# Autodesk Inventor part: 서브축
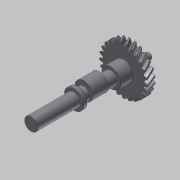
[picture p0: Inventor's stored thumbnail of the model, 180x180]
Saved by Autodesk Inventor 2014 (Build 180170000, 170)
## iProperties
Created: 2018-07
Part Number: 서브축
Material: 강철
Document SubType Name: Modeling
Designer: mduedu
Categories: <?xml version="1.0" encoding="UTF-16"?> <MemberInstance><Categories><FamilyTemplate><FamilyTemplateParameter ValueType="xs:double" Id="1" ObjectReferenceKey="da
Density: 7.85 g/cm^3
Mass: 513.764 g
Surface Area: 178.04 cm^2
Volume: 65.4477 cm^3
Appearance: 강철
CustomPartVersion: 1
Author: mduedu
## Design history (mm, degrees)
sketch "Sketch1"
  geometry: C1 r 30.864 at (0, 0)
  constraints: 1 centre point
  dimensions: "d0" = 61.72879 diameter of C1 (= da_da)
extrude "Extrusion1" new body sketch "Sketch1" distance "d1" = 10 (= da_b); taper "d2" = 0 deg
workplane "Work Plane2"
sketch "Sketch2"
  geometry: C1 r 30.864 at (0, 0) reference; C2 r 29.013 at (0, 0)
  constraints: 1 centre point, 1 coincident
  dimensions: "d3" = 58.02632 diameter of C2 (= da_dw)
feature "피치 지름" sketch "Sketch2" dims "d4" = 10, "d5" = 0
workplane "Work Plane8"
workplane "Work Plane9"
feature "스퍼 기어" dims "da_b" = 10, "da_d" = 57.73503, "da_aw" = 44.1, "da_da" = 61.72879, "da_df" = 52.73503, "da_dw" = 58.02632, angle "da_beta" = 30 deg, "da_lefttooth" = 10, "da_righttooth" = 0
sketch "스케치3"
  geometry: C1 r 12.5 at (0, 0); 1 further point
  constraints: 1 centre point, 1 coincident
  dimensions: "d49" = 25 diameter of C1
extrude "돌출2" join sketch "스케치3" distance "d50" = 16; taper "d51" = 0 deg
sketch "스케치4"
  geometry: C1 r 8.5 at (0, 0); 1 further point
  constraints: 1 centre point, 1 coincident
  dimensions: "d52" = 17 diameter of C1
extrude "돌출3" join sketch "스케치4" distance "d53" = 103; taper "d54" = 0 deg
sketch "스케치5"
  geometry: C1 r 7.5 at (0, 0); 1 further point
  constraints: 1 centre point, 1 coincident
  dimensions: "d55" = 15 diameter of C1
extrude "돌출4" join sketch "스케치5" distance "d56" = 16; taper "d57" = 0 deg
sketch "스케치6"
  geometry: C1 r 4 at (0, 0); 1 further point
  constraints: 1 centre point, 1 coincident
  dimensions: "d58" = 8 diameter of C1
extrude "돌출5" join sketch "스케치6" distance "d59" = 7; taper "d60" = 0 deg
chamfer "모따기1" distance "d61" = 0.5; stored, may be unused: second distance "d62" = 2, angle "d63" = 45 deg
fillet "모깎기1" dims "d64" = 0.5
node "작업 평면11"
sketch "스케치7"
  geometry: C1 r 8.5 at (0, 0) reference; C2 r 11.5 at (0, -3); 1 further point
  constraints: 1 centre point, 1 tangent, 1 vertical alignment
  dimensions: "d66" = 23 diameter of C2; "d67" = 3 distance of point (0, 0) C2.centre (derived)
extrude "돌출6" join sketch "스케치7" stored distance "d68" = 20; taper "d69" = 0 deg
node "작업 평면12"
sketch "스케치8"
  geometry: C1 r 12.5 at (0, 0) reference; C2 r 12.5 at (0, 0) reference; 1 further point
extrude "돌출7" join sketch "스케치8" distance "d71" = 5; taper "d72" = 0 deg
chamfer "모따기2" distance "d73" = 0.5; stored, may be unused: second distance "d74" = 2, angle "d75" = 45 deg
body "Solid1"
body "Srf1"
node "투영된 루프1"
other parameters: "d16" = 44.1 (= da_aw), "d17" = 0, "d34" = 1.25664 (computed from da_z), "d39" = 0, "d41" = 0, "d43" = 44.1 (= da_aw), "d46" = 44.1 (= da_aw), "d47" = 0, "d48" = 0, "d65" = 25, "d70" = 48
